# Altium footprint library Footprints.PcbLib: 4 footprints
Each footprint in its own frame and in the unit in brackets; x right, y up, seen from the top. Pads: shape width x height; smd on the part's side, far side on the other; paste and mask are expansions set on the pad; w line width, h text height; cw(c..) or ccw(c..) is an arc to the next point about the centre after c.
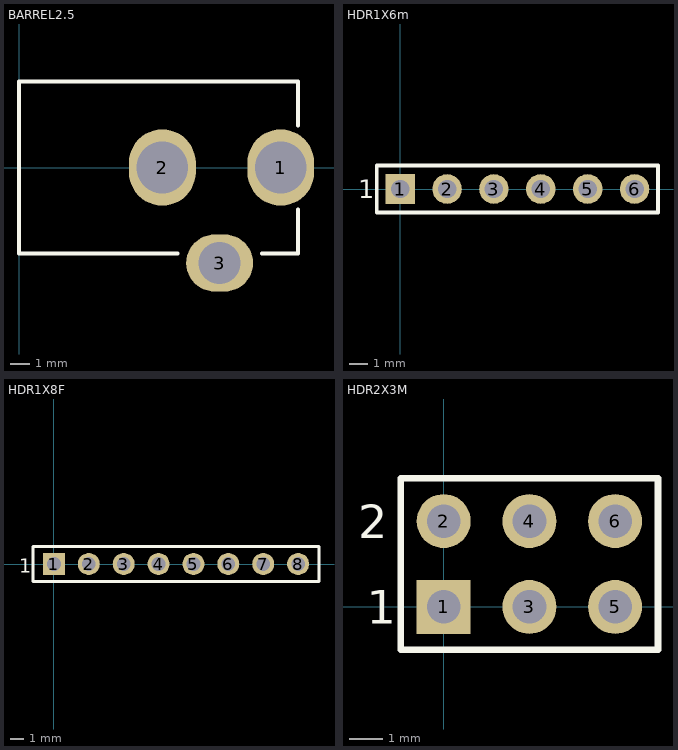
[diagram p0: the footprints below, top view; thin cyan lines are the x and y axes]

## BARREL2.5 [mm] "DC Power Jack, 2.5mm, KLD Series, PCB Mount"
height 11
pads (3):
  oval 3.5x4 hole 2.7: 1(13.7,0) 2(7.5,0)
  oval 3.5x3 hole 2.2: 3(10.5,-5)
Top Overlay:
  lines w0.2: 8.3,-4.5 0,-4.5 0,4.5 14.6,4.5 14.6,2.2 ; 12.7,-4.5 14.6,-4.5 14.6,-2.2
3D body: height 5, standoff -0.05, extent 2.223,-4.445 14.54,4.5
3D body: height 10.5, standoff 1.5, extent 2.54,-4.445 14.54,4.555
3D body: height 11, standoff -0.05, extent 0,-4.445 3.175,4.555

## HDR1X6m [mm] "Connector; Header; 6 Position"
pads (6):
  rect 1.6x1.6 hole 1: 1(0,0)
  round 1.6 hole 1: 2(2.54,0) 3(5.08,0) 4(7.62,0) 5(10.16,0) 6(12.7,0)
Top Overlay:
  lines w0.2: -1.27,-1.27 13.97,-1.27 13.97,1.27 -1.27,1.27 -1.27,-1.27
  text "1" at -2.286,-0.508 h1
3D body "User Library-1x6 TH Pitch 2_54mm.step": height 9.55, standoff -3.15, extent -1.27,-1.27 13.97,1.27

## HDR1X8F [mm] "Connector; Header; 8 Position"
pads (8):
  rect 1.6x1.6 hole 1: 1(0,0)
  round 1.6 hole 1: 2(2.54,0) 3(5.08,0) 4(7.62,0) 5(10.16,0) 6(12.7,0) 7(15.24,0) 8(17.78,0)
Top Overlay:
  lines w0.2: -1.52,-1.27 19.3,-1.27 19.3,1.27 -1.52,1.27 -1.52,-1.27
  text "1" at -2.54,-0.635 h1
3D body "User Library-Header _Fem_1X8.step": height 8.55, standoff -3.15, extent -1.52,-1.27 19.3,1.27

## HDR2X3M [mm] "Connector; Header; 3x2 Position"
pads (6):
  rect 1.6x1.6 hole 1: 1(0,0)
  round 1.6 hole 1: 2(0,2.54) 3(2.54,0) 4(2.54,2.54) 5(5.08,0) 6(5.08,2.54)
Top Overlay:
  lines w0.2: 1.482,-1.27 6.35,-1.27 ; 6.35,-1.27 -1.27,-1.27 -1.27,3.81 6.35,3.81 6.35,-1.27
  text "1" at -2.286,-0.508 h1
  text "2" at -2.54,2.032 h1
3D body "User Library-2x3 Header.step": height 8.5, standoff -3, extent -1.27,-1.27 6.35,3.77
